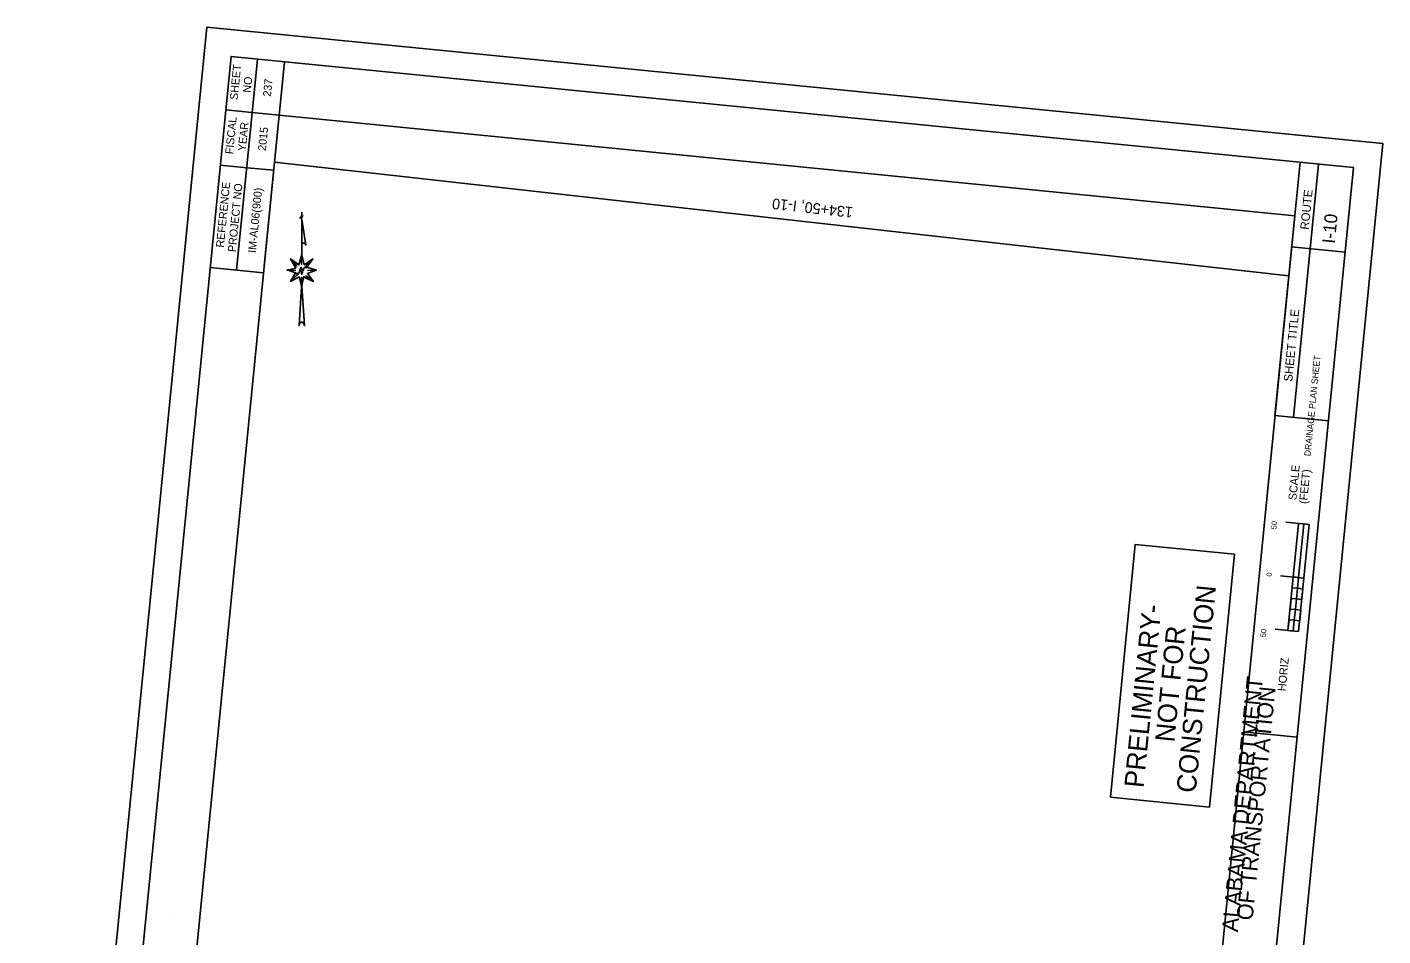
# Model space of a CAD drawing. Extents: x 1797076 to 1798338, y 246730 to 248530.
# Drawn here: x 1797076 to 1798338, y 247685 to 248530 of the extents above; entities that cross this region are included whole.
import ezdxf

# ---------------------------------------------------------------- set-up
doc = ezdxf.new("R2010")
doc.units = 0
for name, color, linetype in [('1', 7, 'Continuous'), ('29', 7, 'Continuous'), ('ANNO-SHT', 7, 'Continuous'), ('ANNO-SYMB', 7, 'Continuous'), ('ANNO-TXT', 7, 'Continuous'), ('DRAINAGE', 7, 'Continuous'), ('Level 1', 7, 'Continuous'), ('Level 57', 7, 'Continuous'), ('Level 6', 7, 'Continuous'), ('Level 62', 7, 'Continuous'), ('SHT-BDR', 7, 'Continuous'), ('SHT-BNDRY', 7, 'Continuous')]:
    doc.layers.add(name, color=color, linetype=linetype)

# ---------------------------------------------------------------- blocks, each defined once
blk = doc.blocks.new('SC47208')
at = {"layer": 'Level 1'}
blk.add_line((0, 0), (0, 0), dxfattribs=at)

msp = doc.modelspace()

# ---------------------------------------------------------------- linework, layer by layer
at = {"layer": '1'}
msp.add_lwpolyline([(1798084.6, 247813.7), (1798107.8, 248048.9), (1798200, 248039.8), (1798176.7, 247804.5)], close=True, dxfattribs=at)
at = {"layer": '29'}
msp.add_line((1797306.5, 248404.6), (1798250.6, 248298.9), dxfattribs=at)
at = {"layer": 'ANNO-SYMB'}
for p, q in [((1798269.7, 248067.4), (1798247.8, 248069.5)), ((1798259.7, 248068.3), (1798249.9, 247968.8)), ((1798269.7, 248067.4), (1798259.8, 247967.8)), ((1798269.7, 248067.4), (1798264.7, 248067.9)), ((1798269.7, 248067.4), (1798264.7, 248067.9)), ((1798269.7, 248067.4), (1798264.7, 248067.9)), ((1798264.7, 248017.6), (1798242.9, 248019.8)), ((1798264.7, 248017.6), (1798242.9, 248019.8)), ((1798264.7, 248017.6), (1798242.9, 248019.8)), ((1798259.8, 248018.1), (1798254.8, 248018.6)), ((1798259.8, 248018.1), (1798254.8, 248018.6)), ((1798259.8, 248018.1), (1798254.8, 248018.6)), ((1798259.8, 248018.1), (1798257.8, 247998.2)), ((1798259.8, 247967.8), (1798237.9, 247970)), ((1798255.8, 247978.3), (1798250.9, 247978.8)), ((1798255.8, 247978.3), (1798250.9, 247978.8))]:
    msp.add_line(p, q, dxfattribs=at)
for points in [[(1798259.8, 248018.1), (1798264.7, 248067.9), (1798269.7, 248067.4), (1798264.7, 248017.6)], [(1798253.8, 248008.6), (1798254.8, 248018.6), (1798259.8, 248018.1), (1798258.8, 248008.1)], [(1798257.8, 247998.2), (1798258.8, 248008.1), (1798263.8, 248007.7), (1798262.8, 247997.7)], [(1798251.8, 247988.7), (1798252.8, 247998.7), (1798257.8, 247998.2), (1798256.8, 247988.2)], [(1798255.8, 247978.3), (1798256.8, 247988.2), (1798261.8, 247987.7), (1798260.8, 247977.8)], [(1798249.9, 247968.8), (1798250.9, 247978.8), (1798255.8, 247978.3), (1798254.8, 247968.3)]]:
    msp.add_lwpolyline(points, close=True, dxfattribs=at)
at = {"layer": 'ANNO-TXT'}
for p, q in [((1798270.6, 248324.1), (1798278.4, 248402.8)), ((1798255.1, 248167.3), (1798270.6, 248324.1))]:
    msp.add_line(p, q, dxfattribs=at)
at = {"layer": 'Level 57'}
msp.add_line((1797331.9, 248358.2), (1797331.8, 248355.7), dxfattribs=at)
for points in [[(1797333, 248354.6), (1797332.9, 248354.6), (1797333, 248354.4), (1797333.1, 248354.6), (1797333, 248354.7), (1797332.8, 248354.7), (1797332.6, 248354.6), (1797332.4, 248354.5), (1797332.2, 248354.1), (1797332.1, 248353.7), (1797331.9, 248353.1), (1797331.8, 248353), (1797331.7, 248352.6), (1797331.7, 248353.2), (1797331.7, 248354.1), (1797331.5, 248354.7), (1797331.5, 248354.1), (1797331.7, 248352.6), (1797331.7, 248354.1), (1797331.5, 248354.7), (1797331.3, 248354.2), (1797330.9, 248353.1), (1797330.6, 248352.6), (1797330.4, 248352.5), (1797330.2, 248352.5), (1797330.1, 248352.6), (1797330.1, 248352.8), (1797330.2, 248352.9), (1797330.3, 248352.8), (1797330.2, 248352.7)], [(1797331.8, 248351.6), (1797335.5, 248327.5), (1797335.3, 248328.3), (1797335.1, 248328.6), (1797334.7, 248328.9), (1797334.2, 248329.2), (1797333.9, 248329.2), (1797333.5, 248329.2), (1797333.1, 248329.3), (1797332.8, 248329.1), (1797332.5, 248329), (1797332.2, 248328.7), (1797332, 248328.5), (1797331.9, 248328.2), (1797331.8, 248328), (1797331.8, 248351.5), (1797331.9, 248318.6)], [(1797331.9, 248318.6), (1797331.7, 248309.7), (1797331.9, 248318.7), (1797329.2, 248309.1), (1797321.3, 248314.6), (1797327.4, 248307.9), (1797321.3, 248314.6), (1797326.2, 248306.1), (1797318.2, 248304.1), (1797325.9, 248303.9), (1797318.3, 248304.3), (1797326.1, 248301.5), (1797321.5, 248293.6), (1797327.3, 248299.4), (1797321.5, 248293.6), (1797329.4, 248298), (1797331.7, 248289.1), (1797331.6, 248297.4), (1797331.7, 248288.9), (1797333.7, 248297.9), (1797342.7, 248293.7), (1797333.6, 248297.9), (1797331.7, 248288.6), (1797329.4, 248252.6), (1797329.6, 248253.8), (1797329.9, 248254.6), (1797330.4, 248255.1), (1797331, 248255.5), (1797331.5, 248255.6), (1797332.2, 248255.6), (1797332.7, 248255.4), (1797333.2, 248255.1), (1797333.6, 248254.6), (1797334, 248254), (1797334.1, 248253.5), (1797334.3, 248252.6), (1797331.8, 248289.1), (1797333.6, 248298), (1797342.5, 248293.7), (1797335.7, 248299), (1797342.4, 248293.9), (1797337.2, 248300.9), (1797345.2, 248304), (1797337.6, 248303.9), (1797345.5, 248304), (1797336.7, 248306.8), (1797342.2, 248314.6), (1797335.7, 248308.3), (1797342.2, 248314.6), (1797334.2, 248309.1), (1797332, 248318.5)], [(1797335.7, 248306.6), (1797335.5, 248306.4), (1797335.8, 248306.1), (1797336, 248306.5), (1797335.9, 248306.8), (1797335.8, 248307), (1797335.1, 248306.9), (1797334.5, 248306.6), (1797333.5, 248305.4), (1797333.4, 248304.9), (1797333, 248303.7), (1797332.6, 248302.5), (1797332.1, 248301.6), (1797331.9, 248300.2), (1797331.9, 248302), (1797331.7, 248304.2), (1797331.6, 248305.4), (1797331.1, 248306.8), (1797331.1, 248305.1), (1797331.4, 248302.9), (1797331.6, 248301.4), (1797331.9, 248300.3), (1797331.9, 248302.3), (1797331.7, 248305.4), (1797331.1, 248306.9), (1797330.8, 248305.4), (1797330.2, 248303.8), (1797329.9, 248303.1), (1797329.6, 248302.3), (1797329.2, 248301.5), (1797328.9, 248301), (1797328.7, 248300.4), (1797327.8, 248300.1), (1797327.2, 248300.2), (1797327, 248300.5), (1797326.9, 248301.2), (1797327.3, 248301.5), (1797327.6, 248301.1), (1797327.4, 248300.9)]]:
    msp.add_lwpolyline(points, dxfattribs=at)
at = {"layer": 'Level 6'}
for p, q in [((1797290.6, 248500.6), (1797271.2, 248304.2)), ((1797315.7, 248498.1), (1797296.9, 248307.8)), ((1797285.3, 248450.8), (1797261.1, 248453.2)), ((1797285.3, 248450.8), (1797310.8, 248448.3)), ((1797280.9, 248399.5), (1797256, 248402)), ((1797280.9, 248399.5), (1797305.7, 248397.1)), ((1798261.1, 248404.5), (1798237.8, 248169)), ((1797246.6, 248306.7), (1797296.3, 248301.7))]:
    msp.add_line(p, q, dxfattribs=at)
at = {"layer": 'Level 62'}
msp.add_lwpolyline([(1798170.8, 246730.3), (1798338.2, 248422), (1797243.6, 248530.3), (1797076.2, 246838.6)], close=True, dxfattribs=at)
at = {"layer": 'SHT-BDR'}
msp.add_lwpolyline([(1798108.5, 246862), (1798256.2, 248354.7), (1797310.8, 248448.3), (1797163.1, 246955.6)], close=True, dxfattribs=at)
at = {"layer": 'SHT-BNDRY'}
for p, q in [((1798303.1, 248320.9), (1798253.3, 248325.8)), ((1798287.6, 248164), (1798237.8, 248169)), ((1798258.5, 247869.5), (1798208.6, 247874.5))]:
    msp.add_line(p, q, dxfattribs=at)
msp.add_lwpolyline([(1798152.1, 246794.9), (1798310.9, 248399.6), (1797266, 248503), (1797107.2, 246898.3)], close=True, dxfattribs=at)

# ---------------------------------------------------------------- block references
at = {"layer": 'DRAINAGE', "xscale": 1.000002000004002, "yscale": 1.000002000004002, "rotation": -32.06753455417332}
msp.add_blockref('SC47208', (1797211.3, 247706.1), dxfattribs=at)
msp.add_blockref('SC47208', (1797211.3, 247706.1), dxfattribs=at)

# ---------------------------------------------------------------- texts
at = {"layer": '1'}
for s, p in [('CONSTRUCTION', (1798163.9, 247817.1)), ('PRELIMINARY-', (1798115.4, 247821.8)), ('NOT FOR', (1798144.1, 247864.3))]:
    msp.add_text(s, height=18, rotation=84.3491, dxfattribs=at).set_placement(p)
at = {"layer": 'ANNO-SHT'}
for s, height, rotation, p in [('237', 7.45, 84.3491, (1797303.1, 248465.3)), ('2015', 7.45, 84.3491, (1797298.4, 248414.9)), ('IM-AL06(900)', 7.449, 84.3491, (1797289.1, 248319.9)), ('134+50, I-10', 10, 173.6129, (1797845.3, 248362.7)), ('  I-10  ', 12, 84.3491, (1798292.6, 248319.6)), ('               DRAINAGE PLAN SHEET               ', 6, 84.3491, (1798267.6, 248097.5))]:
    msp.add_text(s, height=height, rotation=rotation, dxfattribs=at).set_placement(p)
at = {"layer": 'ANNO-SYMB'}
for s, height, p in [('SCALE', 7.5, (1798257.7, 248089.8)), ('(FEET)', 7.5, (1798267.6, 248086.3)), (' 50', 5, (1798238.9, 248060.8)), ('0', 5, (1798234.7, 248018.7)), ('0', 5, (1798234.7, 248018.7)), ('0', 5, (1798234.7, 248018.7)), (' 50', 5, (1798228.9, 247960.4)), ('HORIZ', 7.5, (1798247.7, 247912))]:
    msp.add_text(s, height=height, rotation=84.4063, dxfattribs=at).set_placement(p)
at = {"layer": 'ANNO-TXT'}
for s, height, p in [('ROUTE', 8, (1798269.2, 248341.5)), ('SHEET TITLE', 8, (1798253.8, 248200)), ('ALABAMA DEPARTMENT', 15, (1798203.2, 247687.7)), ('OF TRANSPORTATION', 15, (1798216.9, 247698.5))]:
    msp.add_text(s, height=height, rotation=84.3491, dxfattribs=at).set_placement(p)
at = {"layer": 'Level 6'}
for s, p in [('SHEET', (1797272.2, 248462.3)), ('NO', (1797284.4, 248469)), ('FISCAL', (1797267.9, 248411.8)), ('YEAR', (1797279.7, 248414.6)), ('REFERENCE', (1797259.3, 248324.9)), ('PROJECT NO', (1797270.4, 248320.7))]:
    msp.add_text(s, height=7.44, rotation=84.3491, dxfattribs=at).set_placement(p)

doc.saveas('drawing.dxf')
